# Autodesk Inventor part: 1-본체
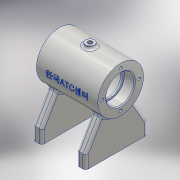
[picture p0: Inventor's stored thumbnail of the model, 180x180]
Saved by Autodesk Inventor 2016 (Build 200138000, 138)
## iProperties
Created: 2018-05
Part Number: 1-본체
Material: 알루미늄 6061
Document SubType Name: Modeling
Designer: 201-25
Density: 2.7 g/cm^3
Appearance: 알루미늄 - 평지
Mass: 317.85 g
Surface Area: 375.672 cm^2
Volume: 117.722 cm^3
Author: 201-25
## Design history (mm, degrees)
sketch "스케치1"
  geometry: L1 (-35, 26)-(35, 26); L2 (35, 26)-(35, 0); L3 (35, 0)-(-35, 0); L4 (-35, 0)-(-35, 26); 2 further points
  constraints: 8 end point, 2 midpoint, 2 parallel, 1 horizontal, 1 perpendicular, 1 vertical alignment
  dimensions: "d0" = 52 diameter of L1 L3; "d1" = 70 distance of L1.start L1.end
revolve "회전1" sketch "스케치1" stored, may be unused: angle "d2" = 90 deg
node "작업 평면1"
sketch "스케치3"
  geometry: L1 (-11.906, -10)-(-35, -50); L2 (-35, -50)-(-35, -65); L3 (-35, -65)-(35, -65); L4 (35, -65)-(35, -50); L5 (35, -50)-(11.906, -10); L6 (11.906, -10)-(-11.906, -10); 3 further points
  constraints: 12 end point, 3 perpendicular, 2 midpoint, 2 vertical alignment, 1 horizontal alignment, 1 vertical
  dimensions: "d12" = 70 distance of L2.end L3.end; "d13" = 15 distance of L3.end L4.end; "d14" = 30 deg angle of L4 L5; "d15" = 55 distance between parallel lines of L3 L6; "d16" = 65 distance from line of L3 point (0, 0)
extrude "돌출1" join sketch "스케치3" stored distance "d17" = 10; taper "d18" = 0 deg
sketch "스케치2"
  geometry: L1 (35, 26)-(35, -26) reference; L2 (35, 0)-(23, 0); L3 (23, 0)-(23, -16); L4 (23, -16)-(35, -16); L5 (35, -16)-(35, 0); L6 (23, 0)-(21, 0); L7 (21, 0)-(21, -14); L8 (21, -14)-(23, -14); L9 (23, -14)-(23, 0); L10 (21, 0)-(-21, 0); L11 (-21, 0)-(-21, -21); L12 (-21, -21)-(21, -21); L13 (21, -21)-(21, 0); L14 (-21, 0)-(-23, 0); L15 (-23, 0)-(-23, -14); L16 (-23, -14)-(-21, -14); L17 (-21, -14)-(-21, 0); L18 (-35, 26)-(-35, -26) reference; L19 (-23, 0)-(-35, 0); L20 (-35, 0)-(-35, -16); L21 (-35, -16)-(-23, -16); L22 (-23, -16)-(-23, 0); 1 further point
  constraints: 40 end point, 10 parallel, 5 horizontal, 5 perpendicular, 2 collinear, 1 midpoint, 1 point on line
  dimensions: "d3" = 32 diameter of L4 L2; "d4" = 28 diameter of L8 L10; "d5" = 42 diameter of L12 L10; "d6" = 42 distance of L11.end L12.end; "d7" = 12 distance of L3.end L4.end; "d8" = 2 distance of L15.end L16.end; "d9" = 12 distance of L20.end L21.end
revolve "회전2" sketch "스케치2" stored, may be unused: angle "d10" = 90 deg
node "작업 평면2"
sketch "스케치4"
  geometry: C1 r 5 at (0, 0); 1 further point
  constraints: 1 centre point, 1 coincident
  dimensions: "d20" = 10 diameter of C1
extrude "돌출2" join sketch "스케치4" stored distance "d21" = 10; taper "d22" = 0 deg
sketch "스케치5"
  geometry: L1 (0, 0)-(0, -26.253); L2 (0, 0)-(8.893, -24.432); A1 r 26 centre (0, 0) between (-17.325, -19.386) and (17.325, -19.386) reference; 1 further point
  constraints: 4 end point, 1 coincident, 1 point on circle, 1 vertical
  dimensions: "d24" = 20 deg angle of L1 L2
node "작업 평면4"
  node "작업 평면3"
sketch "스케치7"
  geometry: C1 r 6 at (0, 0); 1 further point
  constraints: 1 centre point, 1 coincident
  dimensions: "d26" = 12 diameter of C1
extrude "돌출3" join sketch "스케치7" stored distance "d27" = 10; taper "d28" = 0 deg
sketch "스케치8"
  geometry: 1 further point
hole "구멍1" sketch "스케치8" at (0, 0) diameter "d29" = 5.188; stored, may be unused: countersink angle "d33" = 90 deg, drill point angle "d35" = 118 deg; dims "d30" = 12, "d31" = 4, "d32" = 2, "d34" = 16
sketch "스케치9"
  geometry: 1 further point
hole "구멍2" sketch "스케치9" at (0, 0) diameter "d36" = 5.188; stored, may be unused: countersink angle "d40" = 90 deg, drill point angle "d42" = 118 deg; dims "d37" = 12, "d38" = 4, "d39" = 2, "d41" = 16
sketch "스케치10"
  geometry: L1 (0, 0)-(-21, 0)
  constraints: 2 end point, 1 horizontal
  dimensions: "d43" = 21 distance of L1.start L1.end
hole "구멍3" sketch "스케치10" at (-21, 0) diameter "d44" = 3.242; stored, may be unused: countersink angle "d48" = 90 deg, drill point angle "d50" = 118 deg; dims "d45" = 8, "d46" = 4, "d47" = 2, "d49" = 10
sketch "스케치11"
  geometry: L1 (5, -15)-(55, -15); L2 (55, -15)-(55, -55); L3 (55, -55)-(5, -55); L4 (5, -55)-(5, -15); L5 (5, -15)-(55, -55); L6 (55, -15)-(5, -55); 2 further points
  constraints: 12 end point, 2 midpoint, 2 parallel, 1 coincident, 1 horizontal, 1 perpendicular
  dimensions: "d54" = 40 distance of L1.end L2.end; "d55" = 50 distance of L2.end L3.end
hole "구멍4" sketch "스케치11" at (55, -15), (5, -15), (5, -55), (55, -55) diameter "d56" = 4.134; stored, may be unused: countersink angle "d60" = 90 deg, drill point angle "d62" = 118 deg; dims "d57" = 8, "d58" = 4, "d59" = 2, "d61" = 10
fillet "모깎기1" dims "d63" = 3
fillet "모깎기2" dims "d64" = 3
fillet "모깎기3" dims "d65" = 3
chamfer "모따기1" distance "d66" = 1; stored, may be unused: second distance "d67" = 2, angle "d68" = 45 deg
fillet "모깎기4" dims "d69" = 3
sketch "스케치12"
  geometry: L1 (-58, 39)-(-58, 91) reference; L2 (-58, 91)-(12, 91) reference; 2 further points
  constraints: 1 other
  dimensions: "d70" = 35 distance from line of L1 point (-23, 65); "d71" = 26 distance from line of point (-23, 65) L2
feature "엠보싱1" sketch "스케치12" dims "d0" = 52, "d1" = 70, "d72" = 0.5, "d73" = 0
fillet "모깎기5" dims "d74" = 0.3
node "솔리드1"
mirror "대칭1"
pattern_circular "원형 패턴1" dims angle "d52" = 360 deg
mirror "대칭2"
other parameters: "d11" = 25, "d19" = 29, "d25" = 3
